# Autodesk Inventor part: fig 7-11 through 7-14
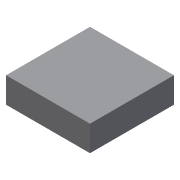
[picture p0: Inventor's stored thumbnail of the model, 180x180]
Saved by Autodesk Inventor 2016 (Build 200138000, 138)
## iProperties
Created: 2009-09
Part Number: fig 7-11 through 7-14
Document SubType Name: Modeling
Designer: Sham
Density: 1 g/cm^3
Material: Generic
Appearance: Default
Author: Sham
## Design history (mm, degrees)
sketch "Sketch1"
  geometry: L1 (-23, 20)-(0, 20); L2 (0, 20)-(0, -3); L3 (0, -3)-(-23, -3); L4 (-23, -3)-(-23, 20)
  constraints: 8 end point, 2 parallel, 1 horizontal, 1 perpendicular
  dimensions: "d2" = 23 distance of L1.start L1.end; "d3" = 23 distance of L3.end L1.start
extrude "Extrusion1" new body sketch "Sketch1" distance "d0" = 7; taper "d1" = 0 deg
body "Solid1"
